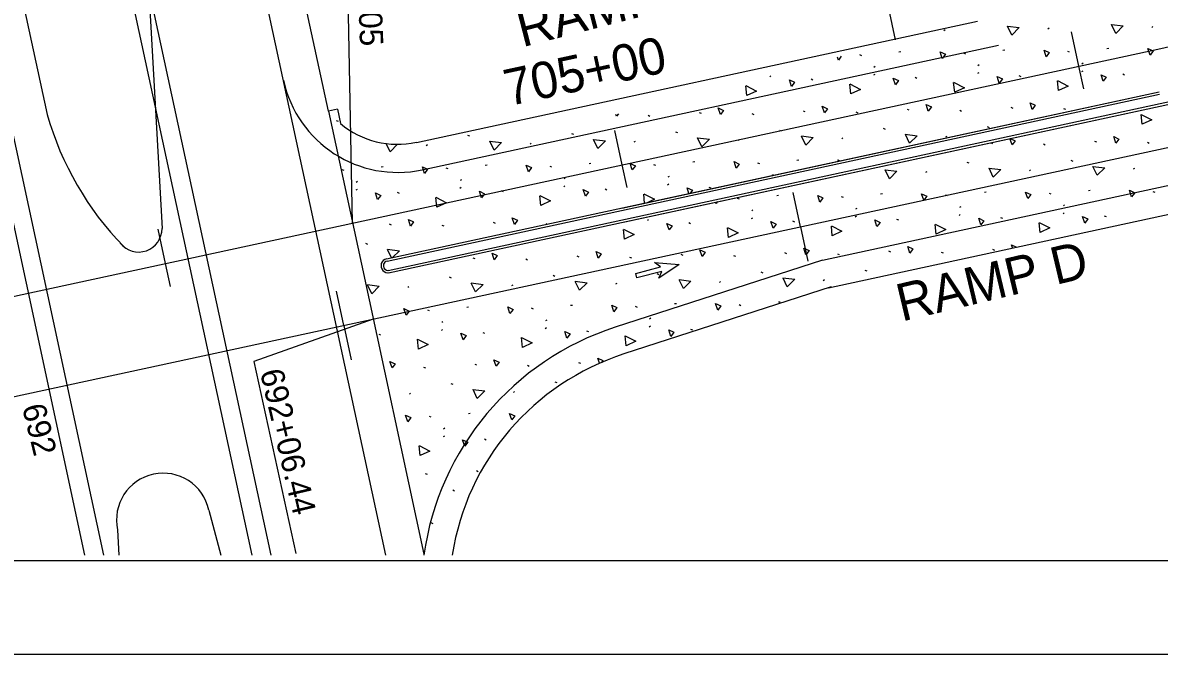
# Model space of a CAD drawing. Extents: x 0 to 1360, y 0 to 880.
# Drawn here: x 166 to 409.3, y 0 to 135 of the extents above; entities that cross this region are included whole.
import ezdxf

# ---------------------------------------------------------------- set-up
doc = ezdxf.new("R2010")
doc.units = 0
for name, color, linetype in [('Default', 7, 'Continuous'), ('PM_P_Cells', 7, 'Continuous'), ('PV_X_Curb', 7, 'Continuous'), ('RD_X_Concrete_Pad', 7, 'Continuous'), ('SH_Border', 7, 'Continuous'), ('SH_Cut_Line', 7, 'Continuous'), ('SH_Text', 7, 'Continuous')]:
    doc.layers.add(name, color=color, linetype=linetype)

# ---------------------------------------------------------------- blocks, each defined once
blk = doc.blocks.new('PMTHRP')
at = {"layer": 'PM_P_Cells'}
for p, q in [((-9.5, -0.5), (-9.5, 0.5)), ((-9.5, 0.5), (-4, 0.5)), ((-9.5, 0), (-9.5, 0)), ((-4, 0.5), (-5, 1.74)), ((-5, 1.74), (0, 0)), ((0, 0), (-5, -1.74)), ((0, 0), (0, 0)), ((-4, -0.5), (-9.5, -0.5)), ((-5, -1.74), (-4, -0.5))]:
    blk.add_line(p, q, dxfattribs=at)

msp = doc.modelspace()

# ---------------------------------------------------------------- linework, layer by layer
at = {"layer": 'Default'}
for p, q in [((243.77, 21.21), (123.28, 579.31)), ((219.22, 21.21), (123.28, 465.59)), ((215.13, 21.21), (123.28, 446.64)), ((183.41, 21.21), (123.28, 299.74)), ((179.32, 21.21), (123.28, 280.79)), ((231.46, 116.15), (199.59, 263.75)), ((155.32, 189.22), (171.25, 115.43)), ((236.63, 92.19), (235.19, 167.58)), ((352.85, 131.38), (350, 144.55)), ((193, 142.63), (195.85, 91.07)), ((385.71, 133.86), (385.44, 133.68)), ((407.94, 134.22), (407.68, 134.04)), ((363.47, 133.5), (363.2, 133.32)), ((392.1, 125.76), (390.52, 133.09)), ((154.52, 74.46), (407.38, 129.06)), ((251.56, 103.6), (374.92, 130.23)), ((376.23, 129.15), (375.83, 129.09)), ((389.65, 128.95), (390.05, 128.78)), ((398.47, 129.51), (398.07, 129.46)), ((345.17, 128.23), (345.58, 128.06)), ((353.99, 128.78), (353.59, 128.73)), ((367.41, 128.59), (367.81, 128.42)), ((348.51, 125.66), (348.24, 125.48)), ((370.67, 124.35), (370.41, 124.16)), ((370.74, 126.02), (370.48, 125.84)), ((393.15, 120.87), (392.1, 125.76)), ((392.91, 124.71), (392.64, 124.53)), ((392.98, 126.39), (392.72, 126.21)), ((401.49, 124.09), (401.89, 123.92)), ((326.19, 123.62), (325.93, 123.44)), ((334.78, 123.01), (335.18, 122.83)), ((348.43, 123.98), (348.17, 123.8)), ((357.02, 123.37), (357.42, 123.2)), ((379.25, 123.73), (379.66, 123.56)), ((377.54, 116.95), (377.95, 116.78)), ((299.88, 115.24), (300.28, 115.07)), ((310.83, 115.87), (311.23, 115.69)), ((322.11, 115.61), (322.52, 115.43)), ((333.07, 116.23), (333.47, 116.06)), ((344.35, 115.97), (344.75, 115.8)), ((355.31, 116.59), (355.71, 116.42)), ((366.59, 116.33), (366.99, 116.16)), ((388.83, 116.69), (389.23, 116.52)), ((233.16, 114.16), (233.56, 113.98)), ((294.35, 104.65), (292.77, 111.98)), ((327.98, 112.1), (328.39, 111.93)), ((350.22, 112.47), (350.62, 112.3)), ((372.46, 112.83), (372.86, 112.66)), ((261.27, 111.02), (261.67, 110.85)), ((283.51, 111.38), (283.91, 111.21)), ((297.12, 109.65), (296.86, 109.47)), ((305.75, 111.74), (306.15, 111.57)), ((319.36, 110.01), (319.1, 109.83)), ((341.6, 110.37), (341.34, 110.19)), ((363.84, 110.73), (363.57, 110.55)), ((395.46, 109.74), (395.87, 109.57)), ((406.75, 109.48), (407.15, 109.31)), ((158.95, 53.94), (411.75, 108.52)), ((252.65, 108.92), (252.39, 108.74)), ((274.89, 109.28), (274.62, 109.1)), ((373.23, 109.38), (373.63, 109.21)), ((384.51, 109.12), (384.91, 108.95)), ((287.65, 104.93), (287.25, 104.88)), ((295.41, 99.77), (294.35, 104.65)), ((301.07, 104.74), (301.47, 104.57)), ((309.89, 105.29), (309.49, 105.24)), ((323.31, 105.1), (323.71, 104.93)), ((332.12, 105.65), (331.73, 105.6)), ((368.14, 105.25), (368.54, 105.08)), ((390.38, 105.62), (390.78, 105.45)), ((234.35, 103.65), (234.76, 103.48)), ((243.17, 104.21), (242.77, 104.15)), ((256.59, 104.01), (257, 103.84)), ((265.41, 104.57), (265.01, 104.52)), ((278.83, 104.38), (279.23, 104.2)), ((304.4, 102.17), (304.14, 101.99)), ((326.64, 102.53), (326.39, 102.36)), ((359.52, 103.16), (359.26, 102.98)), ((381.76, 103.52), (381.5, 103.34)), ((404, 103.89), (403.73, 103.7)), ((237.69, 101.08), (237.42, 100.9)), ((259.85, 99.77), (259.59, 99.59)), ((259.93, 101.45), (259.66, 101.27)), ((282.09, 100.13), (281.83, 99.95)), ((282.16, 101.81), (281.9, 101.63)), ((304.33, 100.49), (304.06, 100.31)), ((312.91, 99.88), (313.31, 99.71)), ((337.24, 84.25), (413.44, 100.7)), ((237.61, 99.41), (237.35, 99.22)), ((246.2, 98.79), (246.6, 98.62)), ((268.44, 99.15), (268.84, 98.98)), ((290.67, 99.52), (291.08, 99.34)), ((318.99, 97.53), (319.39, 97.36)), ((327.81, 98.08), (327.41, 98.03)), ((332.52, 91.41), (330.93, 98.74)), ((341.23, 97.89), (341.63, 97.72)), ((350.04, 98.44), (349.65, 98.39)), ((363.46, 98.25), (363.87, 98.08)), ((372.28, 98.81), (371.88, 98.75)), ((385.7, 98.61), (386.1, 98.44)), ((394.52, 99.17), (394.12, 99.12)), ((407.94, 98.98), (408.34, 98.8)), ((322.32, 94.96), (322.06, 94.78)), ((344.56, 95.32), (344.3, 95.14)), ((366.8, 95.69), (366.53, 95.5)), ((389.04, 96.05), (388.77, 95.87)), ((300.01, 92.92), (299.75, 92.74)), ((322.25, 93.28), (321.98, 93.1)), ((330.83, 92.67), (331.23, 92.49)), ((344.49, 93.64), (344.22, 93.46)), ((353.07, 93.03), (353.47, 92.86)), ((366.72, 94.01), (366.46, 93.82)), ((375.31, 93.39), (375.71, 93.22)), ((388.96, 94.37), (388.7, 94.19)), ((397.54, 93.75), (397.95, 93.58)), ((196.6, 83.55), (195.02, 90.88)), ((244.49, 92.01), (244.89, 91.84)), ((255.77, 91.75), (256.17, 91.58)), ((266.73, 92.38), (267.13, 92.2)), ((278.01, 92.11), (278.32, 91.98)), ((308.59, 92.3), (309, 92.13)), ((332.52, 91.41), (334.1, 84.08)), ((239.4, 87.89), (239.81, 87.72)), ((284.65, 85.16), (285.05, 84.99)), ((306.88, 85.53), (307.29, 85.35)), ((318.17, 85.27), (318.57, 85.09)), ((329.12, 85.89), (329.52, 85.72)), ((340.4, 85.63), (340.81, 85.46)), ((351.36, 86.25), (351.76, 86.08)), ((362.64, 85.99), (363.05, 85.82)), ((373.6, 86.61), (374, 86.44)), ((197.66, 78.66), (196.6, 83.55)), ((262.41, 84.8), (262.81, 84.63)), ((273.69, 84.54), (274.09, 84.37)), ((337.24, 84.25), (292.86, 69.92)), ((295.93, 84.9), (296.33, 84.73)), ((257.32, 80.68), (257.73, 80.51)), ((279.56, 81.04), (279.96, 80.87)), ((301.8, 81.4), (302.2, 81.23)), ((324.04, 81.76), (324.44, 81.59)), ((346.28, 82.13), (346.68, 81.96)), ((248.7, 78.58), (248.44, 78.4)), ((270.94, 78.95), (270.68, 78.76)), ((293.18, 79.31), (292.91, 79.13)), ((315.42, 79.67), (315.15, 79.49)), ((337.65, 80.03), (337.39, 79.85)), ((234.77, 70.31), (233.18, 77.64)), ((252.65, 73.67), (253.05, 73.5)), ((261.46, 74.23), (261.07, 74.18)), ((274.88, 74.04), (275.29, 73.86)), ((283.7, 74.59), (283.3, 74.54)), ((297.12, 74.4), (297.52, 74.23)), ((305.94, 74.95), (305.54, 74.9)), ((319.36, 74.76), (319.76, 74.59)), ((328.18, 75.32), (327.78, 75.26)), ((241.06, 71.66), (215.52, 62.57)), ((255.98, 71.11), (255.72, 70.93)), ((278.22, 71.47), (277.95, 71.29)), ((300.46, 71.83), (300.19, 71.65)), ((234.77, 70.31), (236.35, 62.97)), ((242.25, 68.45), (242.65, 68.28)), ((255.91, 69.43), (255.64, 69.25)), ((264.49, 68.81), (264.89, 68.64)), ((278.14, 69.79), (277.88, 69.61)), ((286.73, 69.18), (287.13, 69)), ((300.38, 70.15), (300.12, 69.97)), ((308.96, 69.54), (309.37, 69.37)), ((215.52, 62.57), (224.49, 21.53)), ((251.82, 61.41), (252.23, 61.24)), ((262.78, 62.04), (263.18, 61.86)), ((274.06, 61.78), (274.46, 61.6)), ((285.02, 62.4), (285.42, 62.23)), ((257.69, 57.91), (258.1, 57.74)), ((271.31, 56.18), (271.05, 56)), ((279.93, 58.27), (280.34, 58.1)), ((249.07, 55.82), (248.81, 55.64)), ((261.84, 51.46), (261.44, 51.41)), ((253.02, 50.91), (253.42, 50.74)), ((256.28, 46.66), (256.01, 46.48)), ((256.35, 48.34), (256.09, 48.16)), ((264.86, 46.05), (265.26, 45.88)), ((263.15, 39.27), (263.55, 39.1)), ((252.2, 38.65), (252.6, 38.48)), ((258.07, 35.15), (258.47, 34.97)), ((249.44, 33.05), (249.4, 33.02)), ((205.89, 30.83), (208.41, 21.21)), ((253.39, 28.14), (253.79, 27.97)), ((186.34, 26.61), (186.62, 21.21))]:
    msp.add_line(p, q, dxfattribs=at)
for points in [[(376.8, 134.31), (379.34, 134), (377.73, 132.38), (376.82, 134.27)], [(399.04, 134.67), (401.58, 134.36), (399.97, 132.74), (399.05, 134.63)], [(384.63, 129.18), (385.75, 128.67), (385.09, 127.77), (384.63, 129.18)], [(406.86, 129.54), (407.98, 129.03), (407.33, 128.13), (406.86, 129.54)], [(341.21, 127.86), (340.62, 127.04), (340.42, 127.66)], [(362.39, 128.82), (363.51, 128.31), (362.86, 127.41), (362.39, 128.82)], [(330.12, 122.84), (331.24, 122.33), (330.59, 121.43), (330.12, 122.84)], [(343.06, 121.94), (345.34, 120.78), (343.27, 119.81), (343.06, 121.9)], [(352.36, 123.2), (353.47, 122.69), (352.82, 121.79), (352.36, 123.2)], [(365.29, 122.3), (367.58, 121.14), (365.51, 120.18), (365.29, 122.26)], [(374.59, 123.57), (375.71, 123.05), (375.06, 122.15), (374.59, 123.57)], [(387.53, 122.67), (389.81, 121.5), (387.74, 120.54), (387.53, 122.62)], [(396.83, 123.93), (397.95, 123.41), (397.3, 122.51), (396.83, 123.93)], [(320.82, 121.58), (323.1, 120.42), (321.03, 119.45), (320.82, 121.53)], [(314.92, 116.81), (316.04, 116.3), (315.39, 115.4), (314.92, 116.81)], [(337.16, 117.17), (338.28, 116.66), (337.63, 115.76), (337.16, 117.17)], [(359.4, 117.54), (360.52, 117.02), (359.87, 116.12), (359.4, 117.54)], [(381.64, 117.9), (382.75, 117.38), (382.1, 116.49), (381.64, 117.9)], [(293.53, 115.55), (293.15, 115.04), (293.02, 115.42)], [(405.45, 115.45), (407.73, 114.29), (405.66, 113.33), (405.45, 115.41)], [(265.98, 109.73), (268.53, 109.42), (266.91, 107.81), (266, 109.69)], [(288.22, 110.09), (290.76, 109.78), (289.15, 108.17), (288.24, 110.05)], [(310.46, 110.46), (313, 110.15), (311.39, 108.53), (310.47, 110.42)], [(332.7, 110.82), (335.24, 110.51), (333.62, 108.89), (332.71, 110.78)], [(354.93, 111.18), (357.48, 110.87), (355.86, 109.25), (354.95, 111.14)], [(377.37, 110.3), (378.44, 109.81), (377.79, 108.91), (377.33, 110.29)], [(399.56, 110.69), (400.68, 110.17), (400.02, 109.27), (399.56, 110.69)], [(246.26, 109.04), (244.67, 107.44), (243.83, 109.2)], [(273.81, 104.6), (274.93, 104.09), (274.28, 103.19), (273.81, 104.6)], [(296.05, 104.97), (297.17, 104.45), (296.51, 103.55), (296.05, 104.97)], [(318.28, 105.33), (319.4, 104.81), (318.75, 103.92), (318.28, 105.33)], [(340.52, 105.69), (340.93, 105.5)], [(340.61, 105.43), (340.52, 105.69)], [(251.57, 104.24), (252.69, 103.73), (252.04, 102.83), (251.57, 104.24)], [(350.62, 103.61), (353.16, 103.3), (351.54, 101.68), (350.63, 103.57)], [(372.85, 103.97), (375.4, 103.66), (373.78, 102.04), (372.87, 103.93)], [(395.09, 104.33), (397.64, 104.02), (396.02, 102.41), (395.11, 104.29)], [(241.54, 98.63), (242.66, 98.11), (242, 97.21), (241.54, 98.63)], [(254.47, 97.73), (256.76, 96.56), (254.69, 95.6), (254.48, 97.68)], [(263.78, 98.99), (264.89, 98.47), (264.24, 97.57), (263.78, 98.99)], [(276.71, 98.09), (279, 96.93), (276.92, 95.96), (276.71, 98.04)], [(286.01, 99.35), (287.13, 98.84), (286.48, 97.94), (286.01, 99.35)], [(298.95, 98.45), (301.23, 97.29), (299.81, 96.62)], [(299.15, 96.48), (298.95, 98.41)], [(308.25, 99.71), (309.37, 99.2), (308.93, 98.59)], [(308.64, 98.53), (308.25, 99.71)], [(336.2, 98.12), (337.32, 97.6), (336.67, 96.7), (336.2, 98.12)], [(358.44, 98.48), (359.56, 97.97), (358.91, 97.07), (358.44, 98.48)], [(380.68, 98.84), (381.8, 98.33), (381.15, 97.43), (380.68, 98.84)], [(402.92, 99.2), (404.04, 98.69), (403.39, 97.79), (402.92, 99.2)], [(314.75, 96.78), (314.43, 96.34), (314.32, 96.69)], [(248.58, 92.96), (249.7, 92.44), (249.05, 91.55), (248.58, 92.96)], [(270.82, 93.32), (271.94, 92.81), (271.29, 91.91), (270.82, 93.32)], [(326.17, 92.5), (327.29, 91.99), (326.64, 91.09), (326.17, 92.5)], [(348.41, 92.86), (349.53, 92.35), (348.88, 91.45), (348.41, 92.86)], [(370.65, 93.23), (371.77, 92.71), (371.11, 91.81), (370.65, 93.23)], [(392.88, 93.59), (394, 93.07), (393.35, 92.17), (392.88, 93.59)], [(294.63, 90.88), (296.92, 89.72), (294.85, 88.75), (294.63, 90.83)], [(303.93, 92.14), (305.05, 91.62), (304.4, 90.73), (303.93, 92.14)], [(316.87, 91.24), (319.15, 90.08), (317.08, 89.11), (316.87, 91.19)], [(339.11, 91.6), (341.39, 90.44), (339.32, 89.47), (339.11, 91.56)], [(361.35, 91.96), (363.63, 90.8), (361.56, 89.84), (361.35, 91.92)], [(383.58, 92.33), (385.87, 91.16), (383.8, 90.2), (383.58, 92.28)], [(244.12, 86.6), (246.66, 86.29), (245.2, 84.83)], [(244.99, 84.79), (244.13, 86.56)], [(266.5, 85.75), (267.62, 85.23), (266.97, 84.33), (266.5, 85.75)], [(288.74, 86.11), (289.86, 85.6), (289.21, 84.7), (288.74, 86.11)], [(310.98, 86.47), (312.1, 85.96), (311.44, 85.06), (310.98, 86.47)], [(333.21, 86.83), (334.33, 86.32), (333.68, 85.42), (333.21, 86.83)], [(355.45, 87.2), (356.57, 86.68), (355.92, 85.78), (355.45, 87.2)], [(377.69, 87.56), (378.75, 87.07)], [(377.91, 86.89), (377.69, 87.56)], [(328.75, 80.48), (331.29, 80.17), (329.68, 78.55), (328.77, 80.44)], [(239.8, 79.03), (242.34, 78.72), (240.73, 77.1), (239.81, 78.99)], [(262.04, 79.39), (264.58, 79.08), (262.96, 77.47), (262.05, 79.35)], [(284.27, 79.75), (286.82, 79.44), (285.2, 77.83), (284.29, 79.71)], [(306.51, 80.12), (309.06, 79.81), (307.44, 78.19), (306.53, 80.08)], [(247.62, 73.9), (248.74, 73.39), (248.09, 72.49), (247.62, 73.9)], [(269.86, 74.26), (270.98, 73.75), (270.33, 72.85), (269.86, 74.26)], [(292.1, 74.63), (293.22, 74.11), (292.57, 73.21), (292.1, 74.63)], [(314.34, 74.99), (315.46, 74.48), (314.8, 73.58), (314.34, 74.99)], [(259.83, 68.65), (260.95, 68.13), (260.3, 67.24), (259.83, 68.65)], [(282.07, 69.01), (283.19, 68.5), (282.53, 67.6), (282.07, 69.01)], [(304.3, 69.37), (305.42, 68.86), (304.77, 67.96), (304.3, 69.37)], [(250.53, 67.39), (252.81, 66.22), (250.74, 65.26), (250.53, 67.34)], [(272.77, 67.75), (275.05, 66.59), (272.98, 65.62), (272.77, 67.7)], [(295, 68.11), (297.29, 66.95), (295.22, 65.98), (295, 68.07)], [(289.11, 63.34), (290.23, 62.83), (289.92, 62.41)], [(289.48, 62.22), (289.11, 63.34)], [(244.63, 62.62), (245.75, 62.1), (245.1, 61.21), (244.63, 62.62)], [(266.87, 62.98), (267.99, 62.47), (267.34, 61.57), (266.87, 62.98)], [(262.41, 56.63), (264.95, 56.32), (263.33, 54.7), (262.42, 56.59)], [(248, 51.14), (249.11, 50.62), (248.46, 49.72), (248, 51.14)], [(270.23, 51.5), (271.35, 50.98), (270.7, 50.09), (270.23, 51.5)], [(250.9, 44.62), (253.18, 43.46), (251.11, 42.49), (250.9, 44.58)], [(260.2, 45.88), (261.32, 45.37), (260.67, 44.47), (260.2, 45.88)]]:
    msp.add_lwpolyline(points, dxfattribs=at)
for centre, radius, start, end in [((246.28, 128.04), 25, 192.1833, 282.1833), ((235.94, 134.05), 67.31, 196.0597, 224.0641), ((190.85, 91.01), 5, 218.2775, 0.647), ((244.22, 83.09), 1.5, 102.1829, 282.1841), ((244.22, 83.09), 1, 102.1829, 282.1841), ((311.3, 12.82), 60, 107.8939, 171.9614), ((196.11, 28.72), 10, 12.1831, 192.1831)]:
    msp.add_arc(centre, radius, start, end, dxfattribs=at)
msp.add_spline([(407.38, 129.06), (432.62, 134.58), (456.13, 140.1), (479.83, 146.42), (503.62, 153.93), (526.94, 163.59), (549.22, 175.79)], degree=3, dxfattribs=at)
at = {"layer": 'PV_X_Curb'}
for p, q in [((244.24, 82.07), (470.75, 130.97)), ((244.34, 81.58), (470.86, 130.49)), ((294.88, 92.49), (470.86, 130.49)), ((243.91, 84.55), (409.28, 120.26)), ((244.01, 84.07), (409.38, 119.77)), ((294.25, 95.42), (409.28, 120.26)), ((409.28, 120.26), (409.3, 120.26)), ((409.28, 120.26), (409.3, 120.26))]:
    msp.add_line(p, q, dxfattribs=at)
at = {"layer": 'RD_X_Concrete_Pad'}
for p, q in [((250.29, 109.46), (370.4, 135.39)), ((233.41, 116.58), (231.46, 116.15)), ((231.46, 116.15), (238.53, 83.39)), ((233.41, 116.58), (234.08, 113.47)), ((338.51, 78.38), (414.7, 94.83)), ((238.53, 83.39), (251.91, 21.4)), ((339.09, 78.54), (294.71, 64.21))]:
    msp.add_line(p, q, dxfattribs=at)
for centre, radius, start, end in [((246.28, 128.04), 19, 230.0465, 282.1833), ((311.3, 12.82), 54, 107.8939, 171.0612)]:
    msp.add_arc(centre, radius, start, end, dxfattribs=at)
at = {"layer": 'SH_Border'}
msp.add_lwpolyline([(60, 860), (1340, 860), (1340, 20), (60, 20)], close=True, dxfattribs=at)
at = {"layer": 'SH_Cut_Line'}
msp.add_lwpolyline([(0, 0), (1360, 0), (1360, 880), (0, 880)], close=True, dxfattribs=at)

# ---------------------------------------------------------------- block references
at = {"layer": 'SH_Text', "rotation": 14.508381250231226}
msp.add_blockref('PMTHRP', (306.57, 83.34), dxfattribs=at)

# ---------------------------------------------------------------- texts
at = {"layer": 'Default'}
for s, height, rotation, p in [('705+59.05', 5, 272.1772, (237.04, 161.71)), ('RAMP CC', 8, 14.4739, (272.96, 129.77)), ('705+00', 7.8, 12.1833, (270.01, 117.18)), ('RAMP D', 8, 13.3788, (354.16, 71.11)), ('692+06.44', 5, 283.1541, (216.79, 60.4)), ('692', 5, 283.9142, (165.85, 52.91))]:
    msp.add_text(s, height=height, rotation=rotation, dxfattribs=at).set_placement(p)

doc.saveas('drawing.dxf')
